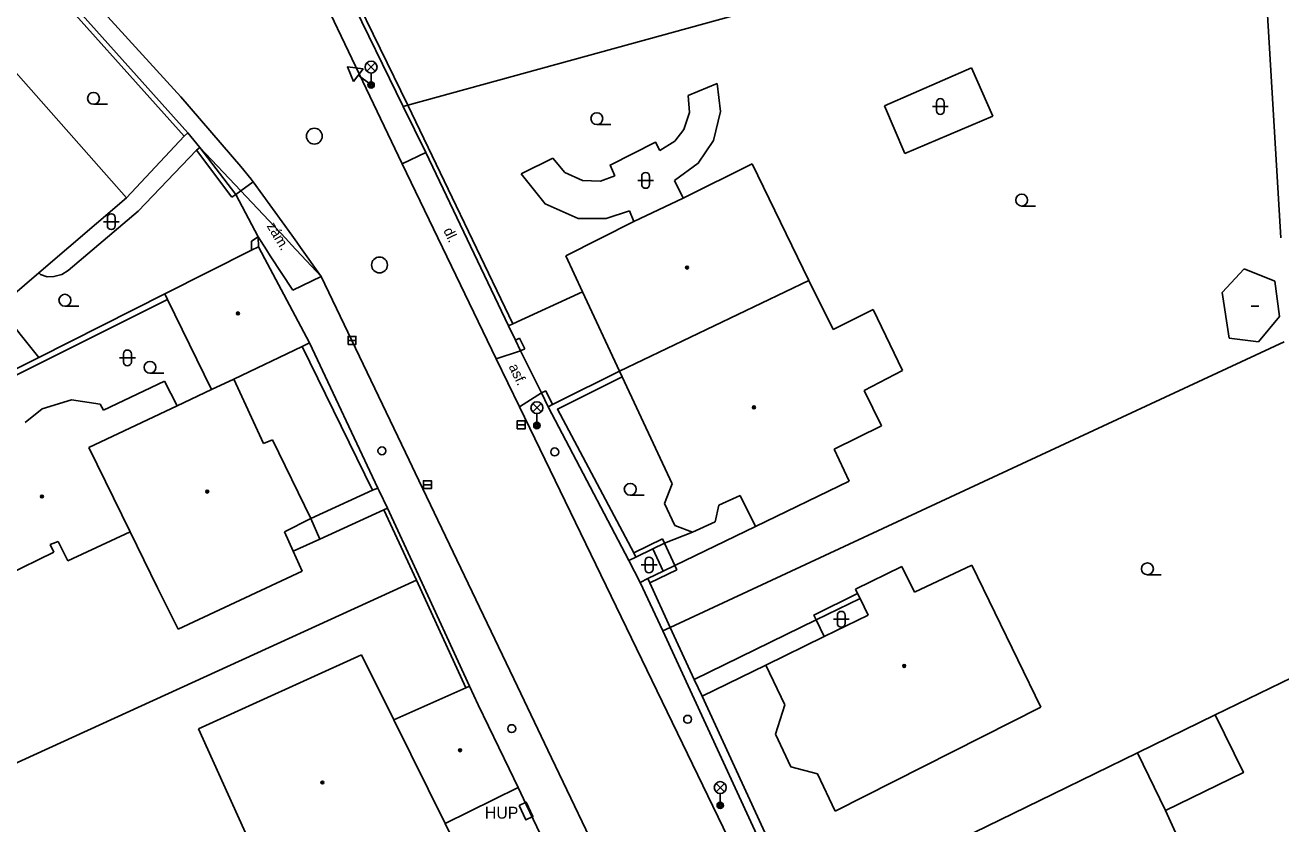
# Model space of a CAD drawing. Extents: x -600391 to -599491, y -1160176 to -1159402.
# Drawn here: x -600102.9 to -600023.5, y -1159577 to -1159526.5 of the extents above; entities that cross this region are included whole.
import ezdxf

# ---------------------------------------------------------------- set-up
doc = ezdxf.new("R2010")
doc.units = 0
for name, color, linetype in [('Level 1', 7, 'Continuous'), ('Level 10', 7, 'Continuous'), ('Level 11', 7, 'Continuous'), ('Level 24', 7, 'Continuous'), ('Level 27', 7, 'Continuous'), ('Level 28', 7, 'Continuous'), ('Level 33', 7, 'Continuous'), ('Level 34', 7, 'Continuous'), ('Level 36', 7, 'Continuous'), ('Level 39', 7, 'Continuous'), ('Level 40', 7, 'Continuous'), ('Level 41', 7, 'Continuous'), ('Level 5', 7, 'Continuous'), ('Level 51', 7, 'Continuous'), ('Level 52', 7, 'Continuous'), ('Level 7', 7, 'Continuous'), ('Level 8', 7, 'Continuous')]:
    doc.layers.add(name, color=color, linetype=linetype)

msp = doc.modelspace()

# ---------------------------------------------------------------- linework, layer by layer
at = {"layer": 'Level 1'}
for points in [[(-600089.24, -1159536.95), (-600091.82, -1159534.21)], [(-600086.4, -1159539.97), (-600089.24, -1159536.95)], [(-600086.4, -1159539.97), (-600089.24, -1159536.95)], [(-600086.04, -1159540.36), (-600086.4, -1159539.97)], [(-600084.15, -1159542.37), (-600086.04, -1159540.36)]]:
    msp.add_lwpolyline(points, dxfattribs=at)
at = {"layer": 'Level 10'}
for points in [[(-600090.16, -1159512.14), (-600083.79, -1159525.29), (-600079.03, -1159535.25)], [(-600101.84, -1159521.34), (-600093.02, -1159531.02)], [(-600093.02, -1159531.02), (-600089.23, -1159535.41), (-600088.58, -1159536.21)], [(-600079.03, -1159535.25), (-600073.09, -1159547.57)], [(-600088.58, -1159536.21), (-600088.46, -1159536.38)], [(-600088.46, -1159536.38), (-600086.023, -1159539.751), (-600085.699, -1159540.199), (-600085.46, -1159540.53), (-600084.15, -1159542.37)], [(-600084.15, -1159542.37), (-600078.59, -1159553.99), (-600078.21, -1159554.79), (-600075.81, -1159559.79), (-600071.75, -1159568.28), (-600069.82, -1159572.31), (-600065.97, -1159580.36), (-600064.36, -1159583.73), (-600057.99, -1159597.02), (-600056.39, -1159600.37), (-600050.66, -1159612.34)], [(-600073.09, -1159547.57), (-600071.61, -1159550.61)], [(-600071.61, -1159550.61), (-600055.214, -1159584.512), (-600053.938, -1159587.149), (-600049.14, -1159597.07)]]:
    msp.add_lwpolyline(points, dxfattribs=at)
at = {"layer": 'Level 11'}
for points in [[(-600060.95, -1159530.92), (-600059.12, -1159530.17)], [(-600059.12, -1159530.17), (-600058.91, -1159531.95), (-600059.35, -1159533.77)], [(-600060.95, -1159530.92), (-600060.88, -1159532), (-600061.23, -1159533.08)], [(-600096.47, -1159537.4), (-600092.81, -1159533.49)], [(-600061.23, -1159533.08), (-600061.81, -1159533.82), (-600062.74, -1159534.4)], [(-600059.35, -1159533.77), (-600060.32, -1159535.21), (-600061.82, -1159536.3)], [(-600095.72, -1159538.25), (-600092.05, -1159534.39)], [(-600077.55, -1159534.53), (-600079.03, -1159535.25)], [(-600065.59, -1159536.01), (-600065.89, -1159535.33), (-600063.02, -1159533.88), (-600062.74, -1159534.4)], [(-600071.52, -1159535.89), (-600069.52, -1159534.9)], [(-600069.52, -1159534.9), (-600068.75, -1159535.79), (-600067.64, -1159536.31)], [(-600071.52, -1159535.89), (-600070, -1159537.77), (-600067.91, -1159538.7)], [(-600067.64, -1159536.31), (-600066.49, -1159536.34), (-600065.59, -1159536.01)], [(-600089.56, -1159537.18), (-600089.24, -1159536.95)], [(-600089.24, -1159536.95), (-600088.46, -1159536.38)], [(-600089.24, -1159536.95), (-600088.46, -1159536.38)], [(-600061.82, -1159536.3), (-600061.27, -1159537.42)], [(-600100.15, -1159542), (-600095.72, -1159538.25)], [(-600067.91, -1159538.7), (-600066.14, -1159538.71), (-600064.66, -1159538.21)], [(-600064.39, -1159538.9), (-600064.66, -1159538.21)], [(-600085.95, -1159543.23), (-600087.373, -1159541.057), (-600087.619, -1159540.681), (-600088.15, -1159539.87)], [(-600100.15, -1159542), (-600100.55, -1159542.25), (-600101.05, -1159542.38), (-600101.48, -1159542.39), (-600101.9, -1159542.25), (-600102, -1159542.14)], [(-600085.95, -1159543.23), (-600084.15, -1159542.37)], [(-600085.95, -1159543.23), (-600084.15, -1159542.37)], [(-600072.04, -1159545.37), (-600067.64, -1159543.33)], [(-600102.01, -1159547.48), (-600104.53, -1159544.35), (-600106.06, -1159545.16)], [(-600073.09, -1159547.57), (-600071.56, -1159547.07)], [(-600071.61, -1159550.61), (-600070.23, -1159549.73)], [(-600080.91, -1159555.88), (-600084.81, -1159557.67)], [(-600080.58, -1159555.74), (-600080.91, -1159555.88)], [(-600084.25, -1159558.97), (-600080.19, -1159557.11)], [(-600080.19, -1159557.11), (-600079.96, -1159557.01)], [(-600084.81, -1159557.67), (-600084.25, -1159558.97)], [(-600056.71, -1159558.18), (-600061.81, -1159560.63)], [(-600085.93, -1159559.73), (-600084.25, -1159558.97)], [(-600064.4, -1159559.84), (-600062.57, -1159558.95)], [(-600063.18, -1159559.58), (-600062.45, -1159559.22)], [(-600062.57, -1159558.95), (-600062.45, -1159559.22)], [(-600062.45, -1159559.22), (-600060.68, -1159558.53)], [(-600062.45, -1159559.22), (-600061.81, -1159560.63)], [(-600064.26, -1159560.11), (-600063.18, -1159559.58)], [(-600062.54, -1159560.99), (-600063.18, -1159559.58)], [(-600061.81, -1159560.63), (-600062.54, -1159560.99)], [(-600061.68, -1159560.91), (-600061.81, -1159560.63)], [(-600063.5, -1159561.46), (-600064, -1159561.71)], [(-600062.54, -1159560.99), (-600063.5, -1159561.46)], [(-600063.37, -1159561.74), (-600061.68, -1159560.91)], [(-600052.86, -1159564.08), (-600053.01, -1159563.77), (-600050.25, -1159562.41)], [(-600052.86, -1159564.08), (-600050.09, -1159562.72)], [(-600052.86, -1159564.08), (-600060.57, -1159567.85)], [(-600052.35, -1159565.12), (-600052.86, -1159564.08)], [(-600056.05, -1159566.93), (-600060.08, -1159568.9)], [(-600032.55, -1159572.48), (-600030.77, -1159576.13), (-600025.85, -1159573.73), (-600027.63, -1159570.08)], [(-600030.77, -1159576.13), (-600029.32, -1159579.32), (-600031.71, -1159580.47)]]:
    msp.add_lwpolyline(points, dxfattribs=at)
at = {"layer": 'Level 24'}
msp.add_lwpolyline([(-600071.645, -1159575.809), (-600071.23, -1159576.719), (-600070.775, -1159576.511), (-600071.19, -1159575.601)], close=True, dxfattribs=at)
at = {"layer": 'Level 27'}
for p, q in [((-600082.46, -1159546.41), (-600081.96, -1159546.41)), ((-600071.76, -1159551.74), (-600071.26, -1159551.74)), ((-600077.69, -1159555.53), (-600077.19, -1159555.53))]:
    msp.add_line(p, q, dxfattribs=at)
for points in [[(-600082.46, -1159546.66), (-600081.96, -1159546.66), (-600081.96, -1159546.16), (-600082.46, -1159546.16)], [(-600071.76, -1159551.99), (-600071.26, -1159551.99), (-600071.26, -1159551.49), (-600071.76, -1159551.49)], [(-600077.69, -1159555.78), (-600077.19, -1159555.78), (-600077.19, -1159555.28), (-600077.69, -1159555.28)]]:
    msp.add_lwpolyline(points, close=True, dxfattribs=at)
for centre in [(-600084.59, -1159533.5), (-600080.47, -1159541.64)]:
    msp.add_circle(centre, 0.5, dxfattribs=at)
at = {"layer": 'Level 28'}
for centre in [(-600080.32, -1159553.39), (-600069.39, -1159553.46), (-600060.99, -1159570.36), (-600072.11, -1159570.95)]:
    msp.add_circle(centre, 0.25, dxfattribs=at)
at = {"layer": 'Level 33'}
for p, q in [((-600081.265, -1159529.4), (-600080.735, -1159528.87)), ((-600081.265, -1159528.87), (-600080.735, -1159529.4)), ((-600081, -1159529.51), (-600081, -1159530.26)), ((-600070.785, -1159550.93), (-600070.255, -1159550.4)), ((-600070.785, -1159550.4), (-600070.255, -1159550.93)), ((-600070.52, -1159551.04), (-600070.52, -1159551.79)), ((-600059.195, -1159574.94), (-600058.665, -1159574.41)), ((-600059.195, -1159574.41), (-600058.665, -1159574.94)), ((-600058.93, -1159575.05), (-600058.93, -1159575.8))]:
    msp.add_line(p, q, dxfattribs=at)
for centre, radius in [((-600081, -1159529.135), 0.375), ((-600081, -1159530.26), 0.2), ((-600081, -1159530.26), 0.145), ((-600081, -1159530.26), 0.0876), ((-600070.52, -1159550.665), 0.375), ((-600070.52, -1159551.79), 0.2), ((-600070.52, -1159551.79), 0.145), ((-600070.52, -1159551.79), 0.0876), ((-600058.93, -1159574.675), 0.375), ((-600058.93, -1159575.8), 0.2), ((-600058.93, -1159575.8), 0.145), ((-600058.93, -1159575.8), 0.0876)]:
    msp.add_circle(centre, radius, dxfattribs=at)
at = {"layer": 'Level 34'}
msp.add_line((-600081.81, -1159529.643), (-600081, -1159530.26), dxfattribs=at)
msp.add_lwpolyline([(-600082.113, -1159530.041), (-600081.507, -1159529.245), (-600082.499, -1159529.118)], close=True, dxfattribs=at)
at = {"layer": 'Level 36'}
for p, q in [((-600045.266, -1159531.376), (-600045.266, -1159531.876)), ((-600044.766, -1159531.376), (-600044.766, -1159531.876)), ((-600098.55, -1159531.485), (-600097.675, -1159531.485)), ((-600045.516, -1159531.626), (-600044.516, -1159531.626)), ((-600066.73, -1159532.765), (-600065.855, -1159532.765)), ((-600063.896, -1159536.046), (-600063.896, -1159536.546)), ((-600063.396, -1159536.046), (-600063.396, -1159536.546)), ((-600064.146, -1159536.296), (-600063.146, -1159536.296)), ((-600039.87, -1159537.915), (-600038.995, -1159537.915)), ((-600097.926, -1159538.906), (-600096.926, -1159538.906)), ((-600097.676, -1159538.656), (-600097.676, -1159539.156)), ((-600097.176, -1159538.656), (-600097.176, -1159539.156)), ((-600100.36, -1159544.245), (-600099.485, -1159544.245)), ((-600096.656, -1159547.266), (-600096.656, -1159547.766)), ((-600096.156, -1159547.266), (-600096.156, -1159547.766)), ((-600096.906, -1159547.516), (-600095.906, -1159547.516)), ((-600094.98, -1159548.485), (-600094.105, -1159548.485)), ((-600064.62, -1159556.195), (-600063.745, -1159556.195)), ((-600063.926, -1159560.606), (-600062.926, -1159560.606)), ((-600063.676, -1159560.356), (-600063.676, -1159560.856)), ((-600063.176, -1159560.356), (-600063.176, -1159560.856)), ((-600031.92, -1159561.225), (-600031.045, -1159561.225)), ((-600051.526, -1159563.786), (-600051.526, -1159564.286)), ((-600051.026, -1159563.786), (-600051.026, -1159564.286)), ((-600051.776, -1159564.036), (-600050.776, -1159564.036))]:
    msp.add_line(p, q, dxfattribs=at)
for centre in [(-600098.55, -1159531.11), (-600066.73, -1159532.39), (-600039.87, -1159537.54), (-600100.36, -1159543.87), (-600094.98, -1159548.11), (-600064.62, -1159555.82), (-600031.92, -1159560.85)]:
    msp.add_circle(centre, 0.375, dxfattribs=at)
for centre, start, end in [((-600045.016, -1159531.376), 0, 180), ((-600045.016, -1159531.876), 180, 0), ((-600063.646, -1159536.046), 0, 180), ((-600063.646, -1159536.546), 180, 0), ((-600097.426, -1159538.656), 0, 180), ((-600097.426, -1159539.156), 180, 0), ((-600096.406, -1159547.266), 0, 180), ((-600096.406, -1159547.766), 180, 0), ((-600063.426, -1159560.356), 0, 180), ((-600063.426, -1159560.856), 180, 0), ((-600051.276, -1159563.786), 0, 180), ((-600051.276, -1159564.286), 180, 0)]:
    msp.add_arc(centre, 0.25, start, end, dxfattribs=at)
at = {"layer": 'Level 39'}
msp.add_line((-600025.37, -1159544.25), (-600024.87, -1159544.25), dxfattribs=at)
for centre, radius in [((-600061.03, -1159541.81), 0.09), ((-600061.03, -1159541.81), 0.0398), ((-600089.42, -1159544.7), 0.09), ((-600089.42, -1159544.7), 0.0398), ((-600056.8, -1159550.64), 0.09), ((-600056.8, -1159550.64), 0.0398), ((-600091.36, -1159555.97), 0.09), ((-600091.36, -1159555.97), 0.0398), ((-600101.81, -1159556.28), 0.09), ((-600101.81, -1159556.28), 0.0398), ((-600047.3, -1159566.99), 0.09), ((-600047.3, -1159566.99), 0.0398), ((-600075.38, -1159572.32), 0.09), ((-600075.38, -1159572.32), 0.0398), ((-600084.08, -1159574.35), 0.09), ((-600084.08, -1159574.35), 0.0398)]:
    msp.add_circle(centre, radius, dxfattribs=at)
at = {"layer": 'Level 5'}
for points in [[(-600106.32, -1159526.25), (-600096.47, -1159537.4)], [(-600061.27, -1159537.42), (-600056.92, -1159535.25)], [(-600056.92, -1159535.25), (-600053.32, -1159542.62)], [(-600096.47, -1159537.4), (-600102, -1159542.14)], [(-600064.39, -1159538.9), (-600061.27, -1159537.42)], [(-600068.69, -1159541.06), (-600064.39, -1159538.9)], [(-600094.04, -1159543.47), (-600088.57, -1159540.71)], [(-600088.57, -1159540.71), (-600088.13, -1159540.49)], [(-600088.13, -1159540.49), (-600087.932, -1159540.863), (-600087.727, -1159541.248), (-600086.527, -1159543.507), (-600084.9, -1159546.57)], [(-600065.3, -1159548.36), (-600067.64, -1159543.33), (-600068.69, -1159541.06)], [(-600102, -1159542.14), (-600103.81, -1159543.7)], [(-600053.32, -1159542.62), (-600065.3, -1159548.36)], [(-600053.32, -1159542.62), (-600051.78, -1159545.72)], [(-600093.87, -1159543.82), (-600094.04, -1159543.47)], [(-600091.1, -1159549.52), (-600093.87, -1159543.82)], [(-600051.78, -1159545.72), (-600049.26, -1159544.45)], [(-600049.26, -1159544.45), (-600047.4, -1159548.31)], [(-600085.37, -1159546.79), (-600089.67, -1159548.85)], [(-600084.9, -1159546.57), (-600085.37, -1159546.79)], [(-600089.67, -1159548.85), (-600091.1, -1159549.52)], [(-600089.67, -1159548.85), (-600087.8, -1159552.93)], [(-600065.13, -1159548.72), (-600065.3, -1159548.36)], [(-600061.97, -1159555.47), (-600065.13, -1159548.72)], [(-600047.4, -1159548.31), (-600049.82, -1159549.57)], [(-600094.07, -1159548.98), (-600097.92, -1159550.81)], [(-600093.27, -1159550.55), (-600094.07, -1159548.98)], [(-600093.27, -1159550.55), (-600091.1, -1159549.52)], [(-600049.82, -1159549.57), (-600048.73, -1159551.8)], [(-600099.95, -1159550.17), (-600101.8, -1159550.74)], [(-600098.12, -1159550.44), (-600099.95, -1159550.17)], [(-600097.92, -1159550.81), (-600098.12, -1159550.44)], [(-600101.8, -1159550.74), (-600102.88, -1159551.59)], [(-600098.85, -1159553.18), (-600093.27, -1159550.55)], [(-600048.73, -1159551.8), (-600051.73, -1159553.29)], [(-600087.8, -1159552.93), (-600087.23, -1159552.7)], [(-600087.23, -1159552.7), (-600084.81, -1159557.67)], [(-600096.24, -1159558.51), (-600098.85, -1159553.18)], [(-600051.73, -1159553.29), (-600050.78, -1159555.3)], [(-600062.45, -1159556.72), (-600061.97, -1159555.47)], [(-600050.78, -1159555.3), (-600056.71, -1159558.18)], [(-600061.8, -1159558.1), (-600062.45, -1159556.72)], [(-600059.01, -1159556.83), (-600059.24, -1159557.87)], [(-600057.66, -1159556.21), (-600059.01, -1159556.83)], [(-600056.71, -1159558.18), (-600057.66, -1159556.21)], [(-600084.81, -1159557.67), (-600086.48, -1159558.51)], [(-600060.68, -1159558.53), (-600061.8, -1159558.1)], [(-600059.24, -1159557.87), (-600060.68, -1159558.53)], [(-600101.3, -1159559.31), (-600100.78, -1159559.13)], [(-600100.78, -1159559.13), (-600100.18, -1159560.35)], [(-600100.18, -1159560.35), (-600096.24, -1159558.51)], [(-600094.51, -1159562.04), (-600096.24, -1159558.51)], [(-600086.48, -1159558.51), (-600085.93, -1159559.73)], [(-600104.08, -1159561.28), (-600101.06, -1159559.8)], [(-600101.06, -1159559.8), (-600101.3, -1159559.31)], [(-600085.93, -1159559.73), (-600085.36, -1159561)], [(-600050.38, -1159562.14), (-600047.45, -1159560.7)], [(-600047.45, -1159560.7), (-600046.65, -1159562.33)], [(-600046.65, -1159562.33), (-600043.03, -1159560.62)], [(-600043.03, -1159560.62), (-600038.66, -1159569.59)], [(-600085.36, -1159561), (-600093.19, -1159564.66)], [(-600093.19, -1159564.66), (-600094.51, -1159562.04)], [(-600050.25, -1159562.41), (-600050.38, -1159562.14)], [(-600050.09, -1159562.72), (-600050.25, -1159562.41)], [(-600049.58, -1159563.77), (-600050.09, -1159562.72)], [(-600052.35, -1159565.12), (-600049.58, -1159563.77)], [(-600056.05, -1159566.93), (-600052.35, -1159565.12)], [(-600091.91, -1159570.96), (-600081.6, -1159566.28)], [(-600081.6, -1159566.28), (-600079.56, -1159570.39)], [(-600054.85, -1159569.45), (-600056.05, -1159566.93)], [(-600079.56, -1159570.39), (-600075.02, -1159568.37)], [(-600075.02, -1159568.37), (-600074.79, -1159568.27)], [(-600074.79, -1159568.27), (-600074.23, -1159569.44), (-600072.27, -1159573.48), (-600071.7, -1159574.66)], [(-600055.44, -1159571.3), (-600054.85, -1159569.45)], [(-600038.66, -1159569.59), (-600051.66, -1159576.17)], [(-600088.45, -1159578.6), (-600091.91, -1159570.96)], [(-600079.56, -1159570.39), (-600076.31, -1159576.95)], [(-600054.46, -1159573.36), (-600055.44, -1159571.3)], [(-600052.78, -1159573.8), (-600054.46, -1159573.36)], [(-600051.66, -1159576.17), (-600052.78, -1159573.8)], [(-600071.7, -1159574.66), (-600076.31, -1159576.95)], [(-600076.31, -1159576.95), (-600075.61, -1159578.41)]]:
    msp.add_lwpolyline(points, dxfattribs=at)
at = {"layer": 'Level 51'}
for points in [[(-600023.48, -1159539.93), (-600024.33, -1159525.83)], [(-600048.55, -1159531.59), (-600043.04, -1159529.18)], [(-600043.04, -1159529.18), (-600041.7, -1159532.23)], [(-600047.25, -1159534.6), (-600048.55, -1159531.59)], [(-600041.7, -1159532.23), (-600047.25, -1159534.6)], [(-600044.99, -1159556.6), (-600023.28, -1159546.51)], [(-600037.91, -1159575.1), (-600032.55, -1159572.48), (-600027.63, -1159570.08), (-600022.78, -1159567.71)], [(-600121.42, -1159581.33), (-600093.07, -1159568.39)]]:
    msp.add_lwpolyline(points, dxfattribs=at)
at = {"layer": 'Level 52'}
for points in [[(-600027.2, -1159543.39), (-600025.81, -1159541.88)], [(-600025.81, -1159541.88), (-600023.86, -1159542.67)], [(-600023.86, -1159542.67), (-600023.57, -1159544.9)], [(-600026.75, -1159546.26), (-600027.2, -1159543.39)], [(-600023.57, -1159544.9), (-600024.89, -1159546.51)], [(-600024.89, -1159546.51), (-600026.75, -1159546.26)]]:
    msp.add_lwpolyline(points, dxfattribs=at)
at = {"layer": 'Level 7'}
for points in [[(-600078.97, -1159531.62), (-600082.45, -1159524.48), (-600088.66, -1159511.46), (-600091.69, -1159505.38)], [(-600078.67, -1159531.54), (-600082.18, -1159524.35), (-600088.39, -1159511.33), (-600091.36, -1159505.37)], [(-600102.16, -1159522.58), (-600092.59, -1159533.29)], [(-600102.4, -1159522.77), (-600092.81, -1159533.49)], [(-600078.67, -1159531.54), (-600055.29, -1159525.12)], [(-600078.97, -1159531.62), (-600078.67, -1159531.54)], [(-600077.55, -1159534.53), (-600078.97, -1159531.62)], [(-600072.04, -1159545.37), (-600078.67, -1159531.54)], [(-600092.81, -1159533.49), (-600092.59, -1159533.29)], [(-600091.82, -1159534.21), (-600092.05, -1159534.39)], [(-600092.05, -1159534.39), (-600089.8, -1159537.36)], [(-600091.82, -1159534.21), (-600089.56, -1159537.18)], [(-600072.31, -1159545.49), (-600077.55, -1159534.53)], [(-600089.8, -1159537.36), (-600089.56, -1159537.18)], [(-600088.15, -1159539.87), (-600088.57, -1159540.14), (-600088.57, -1159540.71)], [(-600088.13, -1159540.49), (-600088.15, -1159539.87)], [(-600114.06, -1159553.55), (-600108.37, -1159550.68), (-600102.01, -1159547.48), (-600094.04, -1159543.47)], [(-600114.06, -1159553.55), (-600113.9, -1159553.81), (-600093.87, -1159543.82)], [(-600072.04, -1159545.37), (-600072.31, -1159545.49)], [(-600071.88, -1159546.4), (-600071.61, -1159546.27)], [(-600071.56, -1159547.07), (-600071.88, -1159546.4)], [(-600071.29, -1159546.94), (-600071.61, -1159546.27)], [(-600085.37, -1159546.79), (-600080.91, -1159555.88)], [(-600084.9, -1159546.57), (-600080.58, -1159555.74)], [(-600071.29, -1159546.94), (-600071.56, -1159547.07)], [(-600069.53, -1159550.46), (-600069.24, -1159550.31), (-600065.3, -1159548.36)], [(-600064.4, -1159559.84), (-600069.22, -1159550.76), (-600065.13, -1159548.72)], [(-600069.96, -1159549.6), (-600070.23, -1159549.73)], [(-600069.53, -1159550.46), (-600069.96, -1159549.6)], [(-600069.8, -1159550.6), (-600070.23, -1159549.73)], [(-600069.8, -1159550.6), (-600069.53, -1159550.46)], [(-600064.71, -1159560.33), (-600069.8, -1159550.6)], [(-600062.09, -1159564.55), (-600044.99, -1159556.6)], [(-600080.19, -1159557.11), (-600078.14, -1159561.57)], [(-600079.96, -1159557.01), (-600078.137, -1159560.98), (-600074.79, -1159568.27)], [(-600064.26, -1159560.11), (-600064.4, -1159559.84)], [(-600064.71, -1159560.33), (-600064.26, -1159560.11)], [(-600093.07, -1159568.39), (-600078.14, -1159561.57)], [(-600078.14, -1159561.57), (-600075.02, -1159568.37)], [(-600063.37, -1159561.74), (-600063.5, -1159561.46)], [(-600062.56, -1159564.77), (-600064, -1159561.71)], [(-600062.09, -1159564.55), (-600063.37, -1159561.74)], [(-600062.56, -1159564.77), (-600062.09, -1159564.55)], [(-600054.15, -1159583.02), (-600062.56, -1159564.77)], [(-600053.68, -1159582.79), (-600060.08, -1159568.9), (-600060.57, -1159567.85), (-600062.09, -1159564.55)], [(-600053.68, -1159582.79), (-600037.91, -1159575.1)], [(-600071.19, -1159575.74), (-600069.41, -1159579.5)]]:
    msp.add_lwpolyline(points, dxfattribs=at)
at = {"layer": 'Level 8'}
for points in [[(-600091.82, -1159534.21), (-600092.59, -1159533.29)], [(-600088.15, -1159539.87), (-600089.56, -1159537.18)], [(-600072.31, -1159545.49), (-600071.88, -1159546.4)], [(-600071.56, -1159547.07), (-600070.23, -1159549.73)], [(-600079.96, -1159557.01), (-600080.49, -1159555.92), (-600080.58, -1159555.74)], [(-600064.71, -1159560.33), (-600064, -1159561.71)], [(-600071.19, -1159575.74), (-600071.7, -1159574.66)]]:
    msp.add_lwpolyline(points, dxfattribs=at)

# ---------------------------------------------------------------- texts
at = {"layer": 'Level 40'}
for s, rotation, p in [('zám.', 300.67, (-600087.62, -1159539.17)), ('dl.', 295.63, (-600076.45, -1159539.46)), ('asf.', 295.68, (-600072.32, -1159548.06))]:
    msp.add_text(s, height=0.65, rotation=rotation, dxfattribs=at).set_placement(p)
at = {"layer": 'Level 41'}
msp.add_text('HUP', height=0.75, dxfattribs=at).set_placement((-600073.81, -1159576.64))
msp.add_text('HUP', height=0.75, dxfattribs=at).set_placement((-600073.81, -1159576.64))

doc.saveas('drawing.dxf')
